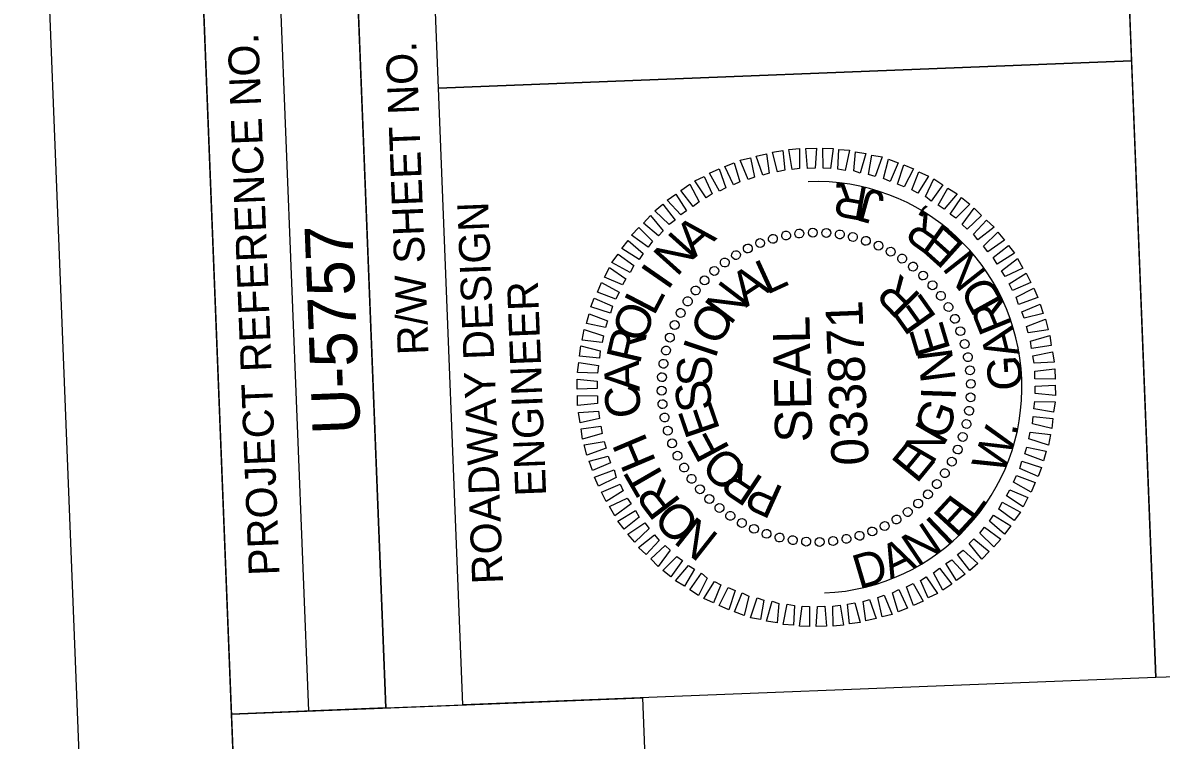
# Model space of a CAD drawing. Extents: x 1627804 to 1628970, y 763730 to 765944.
# Drawn here: x 1627803.6 to 1627988.3, y 765472.6 to 765588.9 of the extents above; entities that cross this region are included whole.
import ezdxf

# ---------------------------------------------------------------- set-up
doc = ezdxf.new("R2010")
doc.units = 0
for name, color, linetype in [('Exist Property Line Text', 7, 'Continuous'), ('Exist Property Owner Number CELL', 7, 'Continuous'), ('Exist Right of Way Monument Leader', 7, 'Continuous'), ('Exist Right of Way Monument Text', 7, 'Continuous'), ('Exist Utilities Gas UG Line', 7, 'Continuous'), ('Exist Utilities Gas UG Line Text', 7, 'Continuous'), ('Raster_Level_0', 7, 'Continuous'), ('Scratch_Level_2', 7, 'Continuous')]:
    doc.layers.add(name, color=color, linetype=linetype)

msp = doc.modelspace()

# ---------------------------------------------------------------- linework, layer by layer
at = {"layer": 'Exist Property Owner Number CELL'}
msp.add_arc((1627932.31, 765529.82), 33.36, 272.2582, 92.2582, dxfattribs=at)
at = {"layer": 'Exist Right of Way Monument Leader'}
msp.add_lwpolyline([(1627845.35, 765276.95), (1627837.47, 765476.85), (1627904.11, 765479.48), (1627911.99, 765279.58)], close=True, dxfattribs=at)
at = {"layer": 'Exist Right of Way Monument Text'}
for p, q in [((1627862.5, 765477.84), (1627854.61, 765677.73)), ((1627850.01, 765477.34), (1627842.12, 765677.24)), ((1627871.04, 765578.3), (1627983.41, 765582.73)), ((1627862.5, 765477.84), (1627874.99, 765478.33))]:
    msp.add_line(p, q, dxfattribs=at)
for points in [[(1627829.58, 765676.74), (1627888.69, 764177.91), (1628937.87, 764219.28), (1628878.77, 765718.12)], [(1627871.04, 765578.3), (1627867.1, 765678.22), (1627979.52, 765682.66), (1627983.46, 765582.73)], [(1627837.47, 765476.85), (1627829.58, 765676.74), (1627854.61, 765677.73), (1627862.5, 765477.84)], [(1627874.99, 765478.33), (1627871.04, 765578.3), (1627983.46, 765582.73), (1627987.4, 765482.76)]]:
    msp.add_lwpolyline(points, close=True, dxfattribs=at)
at = {"layer": 'Exist Utilities Gas UG Line'}
msp.add_lwpolyline([(1628969.75, 764045.4), (1628902.76, 765744.08), (1627803.62, 765700.74), (1627870.6, 764002.06)], close=True, dxfattribs=at)
at = {"layer": 'Exist Utilities Gas UG Line Text'}
for p, q in [((1627987.38, 765482.76), (1627979.5, 765682.65)), ((1628019.34, 765484.02), (1627987.38, 765482.76))]:
    msp.add_line(p, q, dxfattribs=at)
at = {"layer": 'Scratch_Level_2'}
for p, q in [((1627925.25, 765553.92), (1627925.25, 765553.92)), ((1627927.43, 765554.4), (1627927.43, 765554.4)), ((1627929.57, 765554.79), (1627929.57, 765554.79)), ((1627931.77, 765554.92), (1627931.77, 765554.92)), ((1627933.97, 765554.86), (1627933.97, 765554.86)), ((1627936.13, 765554.59), (1627936.13, 765554.59)), ((1627938.25, 765554.23), (1627938.25, 765554.23)), ((1627940.37, 765553.61), (1627940.37, 765553.61)), ((1627921.21, 765552.35), (1627921.21, 765552.35)), ((1627923.18, 765553.23), (1627923.18, 765553.23)), ((1627942.41, 765552.79), (1627942.41, 765552.79)), ((1627944.4, 765551.87), (1627944.4, 765551.87)), ((1627917.45, 765550.05), (1627917.45, 765550.05)), ((1627919.3, 765551.28), (1627919.3, 765551.28)), ((1627946.24, 765550.69), (1627946.24, 765550.69)), ((1627915.75, 765548.74), (1627915.75, 765548.74)), ((1627948.05, 765549.41), (1627948.05, 765549.41)), ((1627914.16, 765547.17), (1627914.16, 765547.17)), ((1627949.65, 765547.97), (1627949.65, 765547.97)), ((1627951.22, 765546.38), (1627951.22, 765546.38)), ((1627912.72, 765545.56), (1627912.72, 765545.56)), ((1627952.54, 765544.68), (1627952.54, 765544.68)), ((1627911.44, 765543.76), (1627911.44, 765543.76)), ((1627953.76, 765542.83), (1627953.76, 765542.83)), ((1627910.26, 765541.92), (1627910.26, 765541.92)), ((1627954.84, 765540.92), (1627954.84, 765540.92)), ((1627909.34, 765539.93), (1627909.34, 765539.93)), ((1627955.71, 765538.95), (1627955.71, 765538.95)), ((1627908.52, 765537.89), (1627908.52, 765537.89)), ((1627907.9, 765535.77), (1627907.9, 765535.77)), ((1627956.4, 765536.88), (1627956.4, 765536.88)), ((1627907.54, 765533.65), (1627907.54, 765533.65)), ((1627956.88, 765534.7), (1627956.88, 765534.7)), ((1627907.27, 765531.49), (1627907.27, 765531.49)), ((1627957.27, 765532.56), (1627957.27, 765532.56)), ((1627932.31, 765529.82), (1627932.31, 765529.82)), ((1627957.4, 765530.36), (1627957.4, 765530.36)), ((1627907.21, 765529.28), (1627907.21, 765529.28)), ((1627957.34, 765528.16), (1627957.34, 765528.16)), ((1627907.34, 765527.09), (1627907.34, 765527.09)), ((1627957.08, 765526), (1627957.08, 765526)), ((1627907.73, 765524.95), (1627907.73, 765524.95)), ((1627908.21, 765522.77), (1627908.21, 765522.77)), ((1627956.71, 765523.88), (1627956.71, 765523.88)), ((1627908.9, 765520.69), (1627908.9, 765520.69)), ((1627956.09, 765521.76), (1627956.09, 765521.76)), ((1627909.77, 765518.73), (1627909.77, 765518.73)), ((1627955.27, 765519.72), (1627955.27, 765519.72)), ((1627910.85, 765516.82), (1627910.85, 765516.82)), ((1627954.35, 765517.73), (1627954.35, 765517.73)), ((1627912.08, 765514.97), (1627912.08, 765514.97)), ((1627953.17, 765515.89), (1627953.17, 765515.89)), ((1627913.39, 765513.27), (1627913.39, 765513.27)), ((1627951.89, 765514.08), (1627951.89, 765514.08)), ((1627914.96, 765511.68), (1627914.96, 765511.68)), ((1627950.45, 765512.48), (1627950.45, 765512.48)), ((1627916.56, 765510.24), (1627916.56, 765510.24)), ((1627947.16, 765509.59), (1627947.16, 765509.59)), ((1627948.86, 765510.91), (1627948.86, 765510.91)), ((1627918.37, 765508.96), (1627918.37, 765508.96)), ((1627920.21, 765507.78), (1627920.21, 765507.78)), ((1627945.31, 765508.37), (1627945.31, 765508.37)), ((1627922.2, 765506.86), (1627922.2, 765506.86)), ((1627924.24, 765506.04), (1627924.24, 765506.04)), ((1627939.36, 765505.73), (1627939.36, 765505.73)), ((1627941.43, 765506.42), (1627941.43, 765506.42)), ((1627943.4, 765507.29), (1627943.4, 765507.29)), ((1627926.36, 765505.42), (1627926.36, 765505.42)), ((1627928.48, 765505.05), (1627928.48, 765505.05)), ((1627930.64, 765504.79), (1627930.64, 765504.79)), ((1627932.84, 765504.73), (1627932.84, 765504.73)), ((1627935.04, 765504.86), (1627935.04, 765504.86)), ((1627937.18, 765505.25), (1627937.18, 765505.25))]:
    msp.add_line(p, q, dxfattribs=at)
for points in [[(1627928.41, 765565.15), (1627927.88, 765568.38), (1627929.58, 765568.55), (1627929.61, 765565.3)], [(1627930.91, 765565.3), (1627930.63, 765568.54), (1627932.33, 765568.61), (1627932.11, 765565.34)], [(1627933.41, 765565.35), (1627933.38, 765568.6), (1627935.03, 765568.56), (1627934.61, 765565.29)], [(1627935.81, 765565.19), (1627935.99, 765568.4), (1627937.69, 765568.27), (1627937.02, 765564.99)], [(1627921.27, 765563.52), (1627919.99, 765566.67), (1627921.63, 765567.03), (1627922.3, 765563.91)], [(1627923.64, 765564.21), (1627922.57, 765567.32), (1627924.26, 765567.69), (1627924.68, 765564.55)], [(1627926.02, 765564.75), (1627925.2, 765567.97), (1627926.89, 765568.19), (1627927.22, 765565)], [(1627938.38, 765564.89), (1627938.66, 765568), (1627940.37, 765567.72), (1627939.44, 765564.53)], [(1627940.8, 765564.34), (1627941.33, 765567.46), (1627942.99, 765567.17), (1627941.87, 765563.98)], [(1627943.23, 765563.68), (1627944.01, 765566.81), (1627945.58, 765566.23), (1627944.3, 765563.17)], [(1627916.59, 765561.63), (1627914.97, 765564.52), (1627916.55, 765565.23), (1627917.67, 765562.17)], [(1627918.9, 765562.62), (1627917.48, 765565.62), (1627919.01, 765566.23), (1627919.93, 765563.16)], [(1627945.47, 765562.77), (1627946.49, 765565.91), (1627948.07, 765565.22), (1627946.59, 765562.31)], [(1627947.81, 765561.86), (1627948.94, 765564.76), (1627950.52, 765564.07), (1627948.78, 765561.3)], [(1627914.48, 765560.55), (1627912.62, 765563.27), (1627914.15, 765563.99), (1627915.41, 765561.18)], [(1627950, 765560.75), (1627951.39, 765563.6), (1627952.83, 765562.66), (1627950.93, 765559.98)], [(1627910.34, 765557.78), (1627908.14, 765560.15), (1627909.55, 765561.15), (1627911.26, 765558.42)], [(1627912.33, 765559.16), (1627910.33, 765561.73), (1627911.79, 765562.74), (1627913.31, 765559.9)], [(1627952.06, 765559.33), (1627953.65, 765562.09), (1627955.14, 765561.2), (1627953.03, 765558.71)], [(1627908.45, 765556.2), (1627906.11, 765558.41), (1627907.42, 765559.52), (1627909.42, 765556.94)], [(1627954.02, 765557.9), (1627955.86, 765560.58), (1627957.2, 765559.53), (1627954.94, 765557.24)], [(1627906.72, 765554.39), (1627904.28, 765556.44), (1627905.44, 765557.69), (1627907.49, 765555.17)], [(1627955.98, 765556.23), (1627957.93, 765558.86), (1627959.13, 765557.65), (1627956.81, 765555.46)], [(1627905.04, 765552.52), (1627902.36, 765554.46), (1627903.51, 765555.71), (1627905.75, 765553.5)], [(1627957.8, 765554.65), (1627959.91, 765556.93), (1627961.15, 765555.78), (1627958.53, 765553.73)], [(1627903.57, 765550.56), (1627900.75, 765552.3), (1627901.79, 765553.64), (1627904.23, 765551.53)], [(1627959.42, 765552.71), (1627961.74, 765554.95), (1627962.84, 765553.65), (1627960.11, 765551.79)], [(1627961, 765550.87), (1627963.47, 765552.82), (1627964.47, 765551.56), (1627961.64, 765549.8)], [(1627902.15, 765548.45), (1627899.18, 765550.08), (1627900.18, 765551.43), (1627902.7, 765549.57)], [(1627962.33, 765548.72), (1627964.96, 765550.68), (1627965.82, 765549.16), (1627962.97, 765547.8)], [(1627900.88, 765546.45), (1627897.97, 765547.69), (1627898.77, 765549.22), (1627901.44, 765547.42)], [(1627963.62, 765546.62), (1627966.35, 765548.33), (1627967.11, 765546.81), (1627964.11, 765545.54)], [(1627899.82, 765544.11), (1627896.82, 765545.24), (1627897.46, 765546.81), (1627900.32, 765545.23)], [(1627964.75, 765544.46), (1627967.6, 765545.88), (1627968.26, 765544.4), (1627965.1, 765543.23)], [(1627898.96, 765541.82), (1627895.76, 765542.84), (1627896.31, 765544.27), (1627899.26, 765542.98)], [(1627965.65, 765542.05), (1627968.6, 765543.31), (1627969.11, 765541.78), (1627966.04, 765541.01)], [(1627898.15, 765539.54), (1627895.02, 765540.16), (1627895.46, 765541.73), (1627898.45, 765540.6)], [(1627966.39, 765539.68), (1627969.5, 765540.85), (1627969.92, 765539.16), (1627966.68, 765538.64)], [(1627897.59, 765537.11), (1627894.32, 765537.48), (1627894.66, 765539.2), (1627897.8, 765538.17)], [(1627967.04, 765537.3), (1627970.2, 765538.22), (1627970.42, 765536.58), (1627967.23, 765536.11)], [(1627897.14, 765534.54), (1627893.93, 765534.87), (1627894.11, 765536.52), (1627897.24, 765535.75)], [(1627967.43, 765534.91), (1627970.61, 765535.59), (1627970.87, 765533.9), (1627967.63, 765533.72)], [(1627896.84, 765532.13), (1627893.58, 765532.2), (1627893.82, 765533.86), (1627896.99, 765533.34)], [(1627967.78, 765532.42), (1627971.02, 765532.8), (1627971.03, 765531.15), (1627967.78, 765531.22)], [(1627896.79, 765529.62), (1627893.54, 765529.5), (1627893.52, 765531.15), (1627896.79, 765530.83)], [(1627967.82, 765530.02), (1627971.07, 765530.15), (1627971.09, 765528.5), (1627967.82, 765528.82)], [(1627896.83, 765527.22), (1627893.59, 765526.85), (1627893.58, 765528.5), (1627896.83, 765528.43)], [(1627897.18, 765524.74), (1627894, 765524.06), (1627893.74, 765525.75), (1627896.98, 765525.93)], [(1627967.77, 765527.52), (1627971.03, 765527.45), (1627970.79, 765525.79), (1627967.62, 765526.31)], [(1627967.47, 765525.11), (1627970.68, 765524.78), (1627970.5, 765523.12), (1627967.37, 765523.9)], [(1627897.57, 765522.35), (1627894.41, 765521.42), (1627894.19, 765523.07), (1627897.38, 765523.54)], [(1627967.02, 765522.54), (1627970.29, 765522.16), (1627969.95, 765520.45), (1627966.81, 765521.48)], [(1627898.22, 765519.97), (1627895.11, 765518.8), (1627894.69, 765520.49), (1627897.93, 765521.01)], [(1627898.96, 765517.6), (1627896.01, 765516.33), (1627895.5, 765517.86), (1627898.57, 765518.64)], [(1627966.46, 765520.11), (1627969.59, 765519.49), (1627969.15, 765517.92), (1627966.16, 765519.05)], [(1627965.65, 765517.83), (1627968.85, 765516.8), (1627968.3, 765515.38), (1627965.35, 765516.67)], [(1627899.86, 765515.18), (1627897.01, 765513.77), (1627896.35, 765515.25), (1627899.51, 765516.42)], [(1627964.79, 765515.54), (1627967.79, 765514.41), (1627967.15, 765512.83), (1627964.29, 765514.42)], [(1627900.99, 765513.03), (1627898.26, 765511.32), (1627897.5, 765512.84), (1627900.5, 765514.11)], [(1627963.73, 765513.2), (1627966.64, 765511.96), (1627965.85, 765510.43), (1627963.17, 765512.23)], [(1627902.28, 765510.93), (1627899.65, 765508.97), (1627898.79, 765510.49), (1627901.64, 765511.85)], [(1627962.46, 765511.2), (1627965.43, 765509.56), (1627964.43, 765508.22), (1627961.91, 765510.08)], [(1627903.61, 765508.78), (1627901.14, 765506.83), (1627900.14, 765508.09), (1627902.97, 765509.85)], [(1627905.19, 765506.94), (1627902.87, 765504.7), (1627901.77, 765506), (1627904.5, 765507.86)], [(1627961.04, 765509.09), (1627963.87, 765507.35), (1627962.82, 765506.01), (1627960.38, 765508.11)], [(1627906.81, 765505), (1627904.7, 765502.72), (1627903.46, 765503.87), (1627906.08, 765505.92)], [(1627959.57, 765507.13), (1627962.25, 765505.19), (1627961.1, 765503.94), (1627958.86, 765506.15)], [(1627908.63, 765503.42), (1627906.68, 765500.79), (1627905.48, 765502), (1627907.8, 765504.19)], [(1627957.89, 765505.26), (1627960.33, 765503.21), (1627959.17, 765501.96), (1627957.12, 765504.48)], [(1627910.59, 765501.75), (1627908.75, 765499.07), (1627907.41, 765500.12), (1627909.67, 765502.41)], [(1627954.27, 765501.87), (1627956.47, 765499.5), (1627955.06, 765498.5), (1627953.35, 765501.23)], [(1627956.16, 765503.44), (1627958.5, 765501.23), (1627957.19, 765500.13), (1627955.19, 765502.71)], [(1627912.55, 765500.32), (1627910.96, 765497.56), (1627909.47, 765498.45), (1627911.58, 765500.94)], [(1627952.28, 765500.49), (1627954.28, 765497.92), (1627952.82, 765496.91), (1627951.31, 765499.75)], [(1627914.61, 765498.9), (1627913.22, 765496.05), (1627911.78, 765496.99), (1627913.68, 765499.67)], [(1627916.81, 765497.79), (1627915.67, 765494.89), (1627914.09, 765495.58), (1627915.83, 765498.35)], [(1627950.13, 765499.1), (1627951.99, 765496.37), (1627950.47, 765495.66), (1627949.2, 765498.47)], [(1627919.14, 765496.88), (1627918.12, 765493.74), (1627916.54, 765494.43), (1627918.02, 765497.34)], [(1627921.38, 765495.97), (1627920.6, 765492.83), (1627919.03, 765493.42), (1627920.31, 765496.48)], [(1627945.71, 765497.03), (1627947.13, 765494.03), (1627945.6, 765493.42), (1627944.68, 765496.49)], [(1627948.02, 765498.02), (1627949.64, 765495.13), (1627948.06, 765494.42), (1627946.94, 765497.48)], [(1627923.81, 765495.31), (1627923.28, 765492.19), (1627921.62, 765492.47), (1627922.74, 765495.67)], [(1627926.23, 765494.76), (1627925.95, 765491.64), (1627924.24, 765491.93), (1627925.17, 765495.12)], [(1627928.8, 765494.46), (1627928.62, 765491.25), (1627926.92, 765491.38), (1627927.59, 765494.66)], [(1627936.2, 765494.5), (1627936.73, 765491.27), (1627935.03, 765491.1), (1627935.01, 765494.35)], [(1627938.59, 765494.89), (1627939.41, 765491.67), (1627937.72, 765491.46), (1627937.4, 765494.65)], [(1627940.97, 765495.44), (1627942.04, 765492.33), (1627940.35, 765491.96), (1627939.93, 765495.1)], [(1627943.34, 765496.13), (1627944.62, 765492.98), (1627942.98, 765492.62), (1627942.31, 765495.74)], [(1627931.2, 765494.3), (1627931.23, 765491.05), (1627929.58, 765491.09), (1627930, 765494.36)], [(1627933.7, 765494.35), (1627933.98, 765491.11), (1627932.28, 765491.04), (1627932.5, 765494.3)]]:
    msp.add_lwpolyline(points, close=True, dxfattribs=at)
for centre, major_axis in [((1627929.57, 765554.75), (-0.078, 0.716)), ((1627931.75, 765554.9), (-0.016, 0.72)), ((1627933.94, 765554.85), (0.047, 0.718)), ((1627923.21, 765553.2), (-0.261, 0.671)), ((1627925.28, 765553.9), (-0.202, 0.691)), ((1627927.41, 765554.42), (-0.141, 0.706)), ((1627936.12, 765554.61), (0.109, 0.712)), ((1627938.26, 765554.19), (0.171, 0.699)), ((1627940.36, 765553.57), (0.231, 0.682)), ((1627942.4, 765552.78), (0.29, 0.659)), ((1627919.29, 765551.26), (-0.374, 0.615)), ((1627921.21, 765552.32), (-0.319, 0.646)), ((1627944.37, 765551.81), (0.346, 0.631)), ((1627917.47, 765550.05), (-0.426, 0.581)), ((1627946.24, 765550.68), (0.4, 0.599)), ((1627948, 765549.39), (0.451, 0.562)), ((1627915.77, 765548.68), (-0.475, 0.541)), ((1627949.65, 765547.94), (0.498, 0.52)), ((1627912.74, 765545.52), (-0.562, 0.451)), ((1627914.19, 765547.16), (-0.52, 0.498)), ((1627951.16, 765546.36), (0.541, 0.475)), ((1627911.45, 765543.76), (-0.599, 0.4)), ((1627952.53, 765544.66), (0.581, 0.426)), ((1627910.32, 765541.88), (-0.631, 0.346)), ((1627953.74, 765542.84), (0.615, 0.374)), ((1627909.35, 765539.92), (-0.659, 0.29)), ((1627954.8, 765540.92), (0.646, 0.319)), ((1627955.68, 765538.92), (0.671, 0.261)), ((1627908.56, 765537.88), (-0.682, 0.231)), ((1627956.38, 765536.85), (0.691, 0.202)), ((1627907.94, 765535.78), (-0.699, 0.171)), ((1627956.9, 765534.72), (0.706, 0.141)), ((1627907.52, 765533.64), (-0.712, 0.109)), ((1627957.24, 765532.56), (0.716, 0.078)), ((1627907.28, 765531.46), (-0.718, 0.047)), ((1627907.23, 765529.27), (-0.72, -0.016)), ((1627957.38, 765530.38), (0.72, 0.016)), ((1627907.37, 765527.09), (-0.716, -0.078)), ((1627957.33, 765528.19), (0.718, -0.047)), ((1627957.09, 765526.01), (0.712, -0.109)), ((1627907.71, 765524.93), (-0.706, -0.141)), ((1627956.67, 765523.87), (0.699, -0.171)), ((1627908.23, 765522.8), (-0.691, -0.202)), ((1627956.06, 765521.77), (0.682, -0.231)), ((1627908.93, 765520.73), (-0.671, -0.261)), ((1627955.26, 765519.73), (0.659, -0.29)), ((1627909.81, 765518.73), (-0.646, -0.319)), ((1627954.3, 765517.76), (0.631, -0.346)), ((1627910.87, 765516.81), (-0.615, -0.374)), ((1627953.16, 765515.89), (0.599, -0.4)), ((1627912.08, 765514.99), (-0.581, -0.426)), ((1627951.87, 765514.13), (0.562, -0.451)), ((1627913.45, 765513.29), (-0.541, -0.475)), ((1627950.42, 765512.48), (0.52, -0.498)), ((1627914.96, 765511.7), (-0.498, -0.52)), ((1627948.84, 765510.97), (0.475, -0.541)), ((1627916.61, 765510.26), (-0.451, -0.562)), ((1627918.37, 765508.97), (-0.4, -0.599)), ((1627947.14, 765509.6), (0.426, -0.581)), ((1627920.25, 765507.83), (-0.346, -0.631)), ((1627922.21, 765506.87), (-0.29, -0.659)), ((1627943.4, 765507.33), (0.319, -0.646)), ((1627945.32, 765508.39), (0.374, -0.615)), ((1627924.25, 765506.07), (-0.231, -0.682)), ((1627926.35, 765505.46), (-0.171, -0.699)), ((1627928.49, 765505.04), (-0.109, -0.712)), ((1627935.04, 765504.89), (0.078, -0.716)), ((1627937.2, 765505.23), (0.141, -0.706)), ((1627939.33, 765505.75), (0.202, -0.691)), ((1627941.4, 765506.45), (0.261, -0.671)), ((1627930.67, 765504.8), (-0.047, -0.718)), ((1627932.86, 765504.75), (0.016, -0.72))]:
    msp.add_ellipse(centre, major_axis=major_axis, ratio=0.999708, dxfattribs=at)

# ---------------------------------------------------------------- texts
at = {"layer": 'Exist Property Line Text'}
msp.add_text('U-5757', height=7.75, rotation=92.2582, dxfattribs=at).set_placement((1627858.39, 765522.32))
at = {"layer": 'Exist Right of Way Monument Text'}
for s, height, p in [('PROJECT REFERENCE NO.', 5.0001, (1627845.28, 765499.37)), ('R/W SHEET NO.', 5.0001, (1627869.44, 765535.15)), ('ROADWAY DESIGN', 5.0001, (1627881.52, 765498)), ('ENGINEER', 5, (1627888.51, 765512.24))]:
    msp.add_text(s, height=height, rotation=92.2582, dxfattribs=at).set_placement(p)
at = {"layer": 'Raster_Level_0'}
for s, height, rotation, p in [('R', 5.5, 169.6122, (1627940.94, 765562.16)), ('.', 5.5, 176.5387, (1627936.98, 765562.97)), ('J', 5.5, 164.7437, (1627943.65, 765561.31)), (',', 5.5, 151.5634, (1627950.53, 765557.89)), ('R', 5.5, 144.637, (1627953.79, 765555.49)), ('E', 5.5, 138.054, (1627956.59, 765552.86)), ('N', 5.5, 128.1223, (1627960.2, 765548.33)), ('D', 5.5, 118.9777, (1627962.78, 765543.66)), ('R', 5.5, 112.0512, (1627964.23, 765539.88)), ('033871', 5.998, 92.2582, (1627940.82, 765517.25)), ('A', 5.5, 103.8654, (1627965.34, 765535.23)), ('G', 5.5, 93.9337, (1627965.77, 765529.46)), ('W', 5.5, 69.1473, (1627962.54, 765515.46)), ('.', 5.5, 80.7534, (1627964.81, 765521.84)), ('E', 5.5, 47.309, (1627955.02, 765505.25)), ('L', 5.5, 53.892, (1627957.69, 765508.01)), ('N', 5.5, 33.8568, (1627948.68, 765500.63)), ('I', 5.5, 43.7885, (1627953.47, 765503.9)), ('A', 5.5, 25.671, (1627944.36, 765498.6)), ('D', 5.5, 16.5264, (1627939.24, 765497.08))]:
    msp.add_text(s, height=height, rotation=rotation, dxfattribs=at).set_placement(p)
at = {"layer": 'Scratch_Level_2'}
for s, height, rotation, p in [('A', 5.64, 40.8753, (1627912.52, 765550.66)), ('N', 5.64, 48.0771, (1627909.69, 765547.6)), ('L', 5.64, 24.659, (1627924.26, 765544.77)), ('I', 5.64, 55.2783, (1627908.22, 765545.39)), ('A', 5.64, 34.0185, (1627920.89, 765542.68)), ('R', 5.64, 134.7396, (1627949.49, 765544.61)), ('N', 5.64, 52.7348, (1627918.4, 765539.73)), ('L', 5.64, 62.4791, (1627905.98, 765541.25)), ('E', 5.64, 125.3823, (1627951.97, 765541.16)), ('O', 5.64, 69.6794, (1627904.31, 765536.78)), ('O', 5.64, 62.0917, (1627916.54, 765536.31)), ('SEAL', 5.998, 91.2582, (1627931.65, 765520.94)), ('R', 5.64, 76.8793, (1627903.69, 765533.4)), ('E', 5.64, 106.67, (1627954.13, 765535.94)), ('I', 5.64, 71.4478, (1627915.92, 765534.28)), ('N', 5.64, 97.3146, (1627954.93, 765531.02)), ('A', 5.64, 91.2785, (1627903.66, 765529.2)), ('S', 5.64, 90.1586, (1627915.39, 765529.96)), ('C', 5.64, 98.4781, (1627904.11, 765525.26)), ('S', 5.64, 99.5138, (1627915.58, 765526.36)), ('I', 5.64, 87.9594, (1627954.91, 765527.66)), ('E', 5.64, 108.8693, (1627916.76, 765522.96)), ('G', 5.64, 69.2484, (1627953.27, 765521.04)), ('N', 5.64, 59.8921, (1627951.17, 765517.16)), ('H', 5.64, 112.8777, (1627906.41, 765517.74)), ('F', 5.64, 118.2252, (1627918.39, 765519.82)), ('E', 5.64, 50.5351, (1627948.59, 765514.05)), ('O', 5.64, 136.9394, (1627921.47, 765516.64)), ('T', 5.64, 120.078, (1627908.19, 765514.56)), ('R', 5.64, 146.2978, (1627923.98, 765514.98)), ('R', 5.64, 127.2787, (1627910.52, 765511.25)), ('P', 5.64, 155.6571, (1627927.24, 765513.51)), ('O', 5.64, 134.4799, (1627913.75, 765507.93)), ('N', 5.64, 141.6817, (1627916.74, 765505.74))]:
    msp.add_text(s, height=height, rotation=rotation, dxfattribs=at).set_placement(p)

doc.saveas('drawing.dxf')
